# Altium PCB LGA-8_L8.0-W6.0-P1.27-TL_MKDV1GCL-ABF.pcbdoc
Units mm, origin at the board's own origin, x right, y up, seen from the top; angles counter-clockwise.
Board outline 22.1 x 18.73 mm, 2 copper layers (Top Layer, Bottom Layer), stack 0.07 mm thick; 1 components, 0 nets, 8 pads, 0 vias.
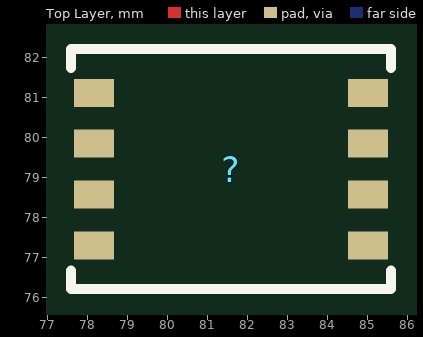
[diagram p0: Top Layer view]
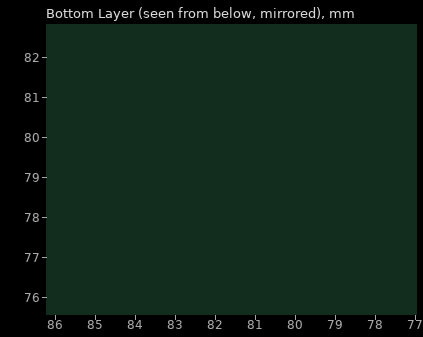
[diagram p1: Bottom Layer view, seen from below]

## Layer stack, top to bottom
Top Solder Mask Layer: solder mask 0.01, Dk 3.3
Top Layer: signal copper 0.035
Bottom Layer: signal copper 0.035
Bottom Solder Mask Layer: solder mask 0.01, Dk 3.3

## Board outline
91.95,69.85 69.85,69.85 69.85,88.58 91.95,88.58

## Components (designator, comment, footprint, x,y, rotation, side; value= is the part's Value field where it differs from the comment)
? "LGA-8_L8.0-W6.0-P1.27-TL_MKDV1GCL-ABF" LGA-8_L8.0-W6.0-P1.27-TL_MKDV1GCL-ABF 81.6,79.2 r0 top

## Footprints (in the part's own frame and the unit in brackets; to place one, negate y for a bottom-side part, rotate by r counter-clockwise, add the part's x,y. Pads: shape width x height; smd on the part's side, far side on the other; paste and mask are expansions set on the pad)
LGA-8_L8.0-W6.0-P1.27-TL_MKDV1GCL-ABF [mm]
  rect 1x0.7 smd paste+0 mask+0.051: 1(-3.425,1.905) 2(-3.425,0.635) 3(-3.425,-0.635) 4(-3.425,-1.905) 5(3.425,-1.905) 6(3.425,-0.635) 7(3.425,0.635) 8(3.425,1.905)
  silkscreen extent -5.4,-3 4,3

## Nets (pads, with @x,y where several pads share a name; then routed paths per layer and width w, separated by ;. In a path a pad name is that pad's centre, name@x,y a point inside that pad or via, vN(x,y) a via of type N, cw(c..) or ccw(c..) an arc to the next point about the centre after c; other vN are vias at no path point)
pads on no net: ?.1 ?.2 ?.3 ?.4 ?.5 ?.6 ?.7 ?.8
